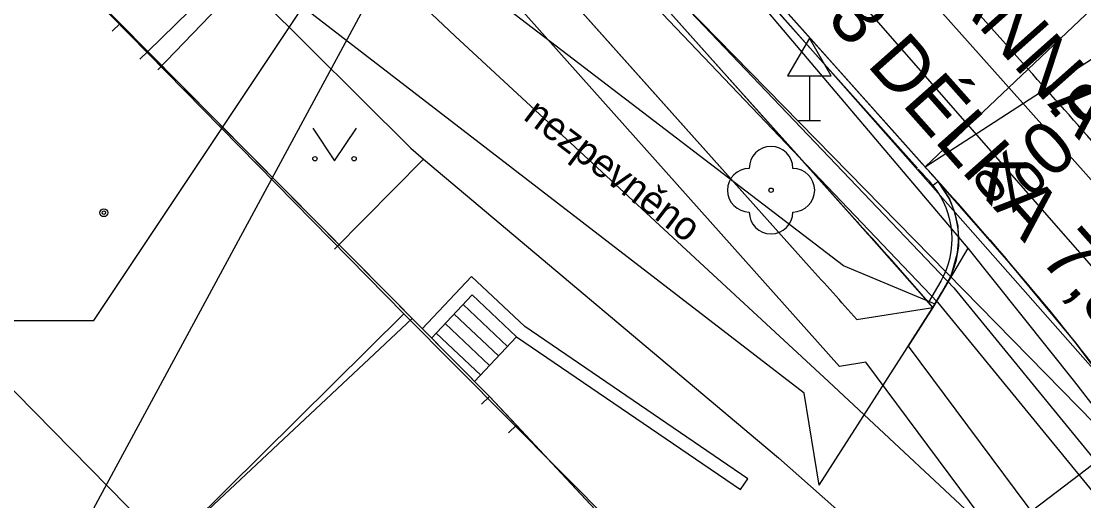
# Model space of a CAD drawing. Extents: x -643342 to -638635, y -1201752 to -1189948.
# Drawn here: x -639555.87 to -639531.53, y -1192591.39 to -1192580.4 of the extents above; entities that cross this region are included whole.
import ezdxf

# ---------------------------------------------------------------- set-up
doc = ezdxf.new("R2010")
doc.units = 0
for name, color, linetype in [('42', 7, 'Continuous'), ('IS_PLYN_STL', 7, 'Continuous'), ('IS_TELEF_MISTNI_ZAMERENO', 7, 'Continuous'), ('IS_VODOVOD_PRIPOJKA DOMOVNÍ', 7, 'Continuous'), ('IS_VODOVOD_VAS', 7, 'Continuous'), ('IS_VODOVOD_ZRUSENY', 7, 'Continuous'), ('K-HRANICE_KN', 7, 'Continuous'), ('N-CHODNIK', 7, 'Continuous'), ('N-KAN_DEST_TRASA-NÁVRH', 7, 'Continuous'), ('N-OBVOD STAVBY 06', 7, 'Continuous'), ('N-OSA', 7, 'Continuous'), ('N-SILNICE', 7, 'Continuous'), ('N-SJEZDY', 7, 'Continuous'), ('N-SO101_KLOPENI', 7, 'Continuous'), ('N-SRAFY_PLOCHY', 7, 'Continuous'), ('N-SVAHOVÁNÍ', 7, 'Continuous'), ('tomaštík - Džuganovi - Vrstva 36', 7, 'Continuous'), ('Z-budovy', 7, 'Continuous'), ('Z-hrany_a_čáry', 7, 'Continuous'), ('Z-popisy', 7, 'Continuous'), ('Z-stromy', 7, 'Continuous'), ('Z-vchody_vjezdy', 7, 'Continuous'), ('Z-značky', 7, 'Continuous')]:
    doc.layers.add(name, color=color, linetype=linetype)

msp = doc.modelspace()

# ---------------------------------------------------------------- linework, layer by layer
at = {"layer": '42'}
for p, q in [((-639555.166, -1192593.331), (-639544.715, -1192573.992)), ((-639540.313, -1192573.957), (-639523.758, -1192592.58)), ((-639554.206, -1192587.256), (-639546.647, -1192575.917)), ((-639601.668, -1192587.256), (-639554.206, -1192587.256))]:
    msp.add_line(p, q, dxfattribs=at)
at = {"layer": 'IS_PLYN_STL'}
msp.add_lwpolyline([(-639559.68, -1192568.38), (-639559.46, -1192568.55), (-639554.43, -1192572.9), (-639553.3, -1192573.86), (-639548.93, -1192577.94), (-639546.47, -1192580.23), (-639545.93, -1192580.74), (-639537.37, -1192588.65), (-639533.32, -1192592.44), (-639527.87, -1192598.3), (-639522.14, -1192604.57), (-639520.58, -1192607.01), (-639519.8, -1192608.6)], dxfattribs=at)
at = {"layer": 'IS_TELEF_MISTNI_ZAMERENO'}
for p, q in [((-639550.79, -1192579.48), (-639552.74, -1192581.51)), ((-639550.79, -1192579.48), (-639546.94, -1192583.31)), ((-639546.94, -1192583.31), (-639546.65, -1192583.56)), ((-639548.69, -1192585.62), (-639546.65, -1192583.56)), ((-639546.65, -1192583.56), (-639538.52, -1192590.4)), ((-639538.52, -1192590.4), (-639534.16, -1192594.26)), ((-639534.16, -1192594.26), (-639538.52, -1192590.4))]:
    msp.add_line(p, q, dxfattribs=at)
at = {"layer": 'IS_VODOVOD_PRIPOJKA DOMOVNÍ'}
msp.add_lwpolyline([(-639531.24, -1192590.494), (-639531.458, -1192590.659), (-639551.224, -1192605.705)], dxfattribs=at)
at = {"layer": 'IS_VODOVOD_VAS'}
for points in [[(-639574.178, -1192545), (-639565.32, -1192554.2), (-639544.196, -1192576.345), (-639543.991, -1192576.56), (-639543.73, -1192576.83), (-639534.504, -1192586.506), (-639531.24, -1192590.494), (-639527.133, -1192595.51), (-639522.796, -1192601.597), (-639522.77, -1192601.637), (-639518.91, -1192607.22), (-639515.881, -1192615.376)], [(-639574.504, -1192545.287), (-639565.62, -1192554.6), (-639534.876, -1192586.834), (-639527.527, -1192595.81), (-639523.229, -1192601.871), (-639519.29, -1192607.54), (-639519.07, -1192608.24), (-639516.818, -1192614.307), (-639515.63, -1192618.18), (-639513.05, -1192632.38), (-639511.6, -1192653.11)]]:
    msp.add_lwpolyline(points, dxfattribs=at)
at = {"layer": 'IS_VODOVOD_ZRUSENY'}
msp.add_lwpolyline([(-639573.944, -1192546.368), (-639550.08, -1192573.56), (-639545.32, -1192575.03), (-639544.04, -1192576.59), (-639530.53, -1192590.38), (-639522.03, -1192601.36), (-639515.23, -1192614.43)], dxfattribs=at)
at = {"layer": 'K-HRANICE_KN'}
for p, q in [((-639524.691, -1192595.875), (-639564.643, -1192550.549)), ((-639524.691, -1192595.875), (-639564.643, -1192550.549)), ((-639547.1, -1192587.1), (-639562.65, -1192571.27)), ((-639545.14, -1192589), (-639561.72, -1192572.25)), ((-639567.14, -1192577.61), (-639552.51, -1192592.45)), ((-639567.14, -1192577.61), (-639552.51, -1192592.45)), ((-639547.1, -1192587.1), (-639552.423, -1192592.372)), ((-639541.039, -1192593.2), (-639547.1, -1192587.1)), ((-639546.916, -1192587.206), (-639552.423, -1192592.372)), ((-639540.559, -1192593.892), (-639545.14, -1192589))]:
    msp.add_line(p, q, dxfattribs=at)
at = {"layer": 'N-CHODNIK'}
for p, q in [((-639536.716, -1192584.996), (-639544.403, -1192576.389)), ((-639536.716, -1192584.996), (-639536.686, -1192585.03)), ((-639534.799, -1192586.357), (-639535.085, -1192586.838)), ((-639534.67, -1192586.433), (-639534.982, -1192586.958))]:
    msp.add_line(p, q, dxfattribs=at)
msp.add_arc((-639605.834, -1192647.866), 93.434, 40.68372, 42.26147, dxfattribs=at)
at = {"layer": 'N-KAN_DEST_TRASA-NÁVRH'}
msp.add_lwpolyline([(-639583.962, -1192528.01), (-639550.452, -1192564.184), (-639529.583, -1192588.026), (-639514.491, -1192612.048), (-639507.737, -1192644.326), (-639498.832, -1192694.254), (-639511.439, -1192713.331), (-639516.613, -1192716.507), (-639553.938, -1192703.739), (-639570.485, -1192701.616), (-639578.687, -1192703.18)], dxfattribs=at)
at = {"layer": 'N-OBVOD STAVBY 06'}
msp.add_lwpolyline([(-639532.853, -1192592.991), (-639532.948, -1192593.015), (-639536.515, -1192588.213), (-639537.119, -1192588.308), (-639546.267, -1192578.054), (-639553.229, -1192570.356), (-639556.749, -1192566.564), (-639568.569, -1192553.875), (-639568.389, -1192552.802), (-639591.813, -1192527.078)], dxfattribs=at)
at = {"layer": 'N-OSA'}
msp.add_lwpolyline([(-639532.8, -1192581.5), (-639540.487, -1192572.892)], dxfattribs=at)
msp.add_arc((-639605.834, -1192647.866), 98.684, 39.35849, 42.26147, dxfattribs=at)
at = {"layer": 'N-SILNICE'}
for p, q in [((-639535.336, -1192583.764), (-639543.023, -1192575.157)), ((-639535.224, -1192583.664), (-639542.911, -1192575.057)), ((-639534.858, -1192584.07), (-639534.974, -1192584.164))]:
    msp.add_line(p, q, dxfattribs=at)
for centre, radius, start, end in [((-639605.834, -1192647.866), 95.434, 39.35849, 42.26147), ((-639605.834, -1192647.866), 95.434, 41.95008, 42.26147), ((-639605.834, -1192647.866), 95.284, 41.95008, 42.26147), ((-639536.489, -1192585.389), 1.948, 330.1366, 38.9464), ((-639536.489, -1192585.389), 1.948, 330.1366, 38.9464), ((-639536.489, -1192585.389), 2.098, 330.1366, 38.9464), ((-639568.444, -1192616.683), 46.75, 36.2973, 38.9025)]:
    msp.add_arc(centre, radius, start, end, dxfattribs=at)
at = {"layer": 'N-SJEZDY'}
for q in [(-639534.982, -1192586.958), (-639532.542, -1192591.885)]:
    msp.add_line((-639535.546, -1192587.841), q, dxfattribs=at)
at = {"layer": 'N-SO101_KLOPENI'}
msp.add_lwpolyline([(-639530.444, -1192579.261), (-639535.156, -1192583.738), (-639529.593, -1192580.131), (-639530.444, -1192579.261)], close=True, dxfattribs=at)
at = {"layer": 'N-SRAFY_PLOCHY'}
for p, q in [((-639536.701, -1192585.014), (-639544.404, -1192576.387)), ((-639545.521, -1192577.388), (-639537.815, -1192586.018)), ((-639539.873, -1192578.459), (-639537.91, -1192580.656)), ((-639537.91, -1192580.656), (-639536.454, -1192582.287)), ((-639536.454, -1192582.287), (-639534.858, -1192584.07)), ((-639534.858, -1192584.07), (-639533.68, -1192585.405)), ((-639533.228, -1192585.931), (-639534.858, -1192584.07)), ((-639534.858, -1192584.07), (-639534.604, -1192584.468)), ((-639534.604, -1192584.468), (-639534.484, -1192584.773)), ((-639534.484, -1192584.773), (-639534.412, -1192585.092)), ((-639534.412, -1192585.092), (-639534.397, -1192585.549)), ((-639533.68, -1192585.405), (-639532.303, -1192587.032)), ((-639534.397, -1192585.549), (-639534.455, -1192585.9)), ((-639534.455, -1192585.9), (-639534.576, -1192586.249)), ((-639531.744, -1192587.723), (-639533.228, -1192585.931)), ((-639534.576, -1192586.249), (-639534.766, -1192586.594)), ((-639534.766, -1192586.594), (-639534.982, -1192586.958)), ((-639536.729, -1192587.234), (-639534.982, -1192586.958)), ((-639534.982, -1192586.958), (-639535.546, -1192587.841)), ((-639532.303, -1192587.032), (-639531.432, -1192588.123)), ((-639535.546, -1192587.841), (-639532.542, -1192591.885)), ((-639530.531, -1192589.336), (-639531.744, -1192587.723))]:
    msp.add_line(p, q, dxfattribs=at)
msp.add_lwpolyline([(-639541.964, -1192579.119), (-639539.83, -1192581.51), (-639538.109, -1192583.436), (-639536.686, -1192585.03), (-639534.982, -1192586.958), (-639534.782, -1192586.622), (-639534.567, -1192586.229), (-639534.416, -1192585.707), (-639534.391, -1192585.368), (-639534.414, -1192585.082), (-639534.487, -1192584.761), (-639534.605, -1192584.466), (-639534.858, -1192584.07), (-639535.863, -1192582.949), (-639537.304, -1192581.336), (-639538.832, -1192579.625)], dxfattribs=at)
for radius, start, end in [(93.434, 40.68372, 42.27523), (91.934, 41.26308, 42.27938)]:
    msp.add_arc((-639605.834, -1192647.866), radius, start, end, dxfattribs=at)
at = {"layer": 'N-SVAHOVÁNÍ'}
msp.add_line((-639536.729, -1192587.234), (-639534.982, -1192586.958), dxfattribs=at)
msp.add_lwpolyline([(-639537.815, -1192586.018), (-639545.521, -1192577.388)], dxfattribs=at)
msp.add_arc((-639605.834, -1192647.866), 91.934, 41.26308, 42.27938, dxfattribs=at)
at = {"layer": 'Z-budovy'}
for p, q in [((-639553.604, -1192580.449), (-639557.02, -1192576.998)), ((-639552.971, -1192581.089), (-639553.604, -1192580.449)), ((-639545.14, -1192589), (-639552.971, -1192581.089)), ((-639544.525, -1192589.657), (-639545.14, -1192589)), ((-639540.559, -1192593.892), (-639544.525, -1192589.657))]:
    msp.add_line(p, q, dxfattribs=at)
at = {"layer": 'Z-hrany_a_čáry'}
for p, q in [((-639534.17, -1192585.6), (-639548.17, -1192569.06)), ((-639537.03, -1192586), (-639548.94, -1192576.89)), ((-639550.82, -1192578.99), (-639552.971, -1192581.089)), ((-639537.93, -1192588.92), (-639550.82, -1192578.99)), ((-639534.93, -1192586.88), (-639534.17, -1192585.6)), ((-639531.73, -1192588.66), (-639534.17, -1192585.6)), ((-639534.93, -1192586.88), (-639537.03, -1192586)), ((-639545.553, -1192586.246), (-639546.68, -1192587.444)), ((-639544.332, -1192587.395), (-639545.553, -1192586.246)), ((-639545.54, -1192586.67), (-639546.469, -1192587.657)), ((-639545.746, -1192586.888), (-639544.726, -1192587.848)), ((-639544.52, -1192587.63), (-639545.54, -1192586.67)), ((-639537.59, -1192591.03), (-639534.93, -1192586.88)), ((-639545.951, -1192587.107), (-639544.931, -1192588.067)), ((-639546.157, -1192587.325), (-639545.137, -1192588.285)), ((-639546.362, -1192587.544), (-639545.342, -1192588.504)), ((-639545.483, -1192588.653), (-639544.52, -1192587.63)), ((-639544.52, -1192587.63), (-639539.39, -1192591.13)), ((-639539.221, -1192590.882), (-639544.332, -1192587.395)), ((-639529.11, -1192592.06), (-639531.73, -1192588.66)), ((-639537.59, -1192591.03), (-639537.93, -1192588.92)), ((-639539.39, -1192591.13), (-639539.221, -1192590.882))]:
    msp.add_line(p, q, dxfattribs=at)
at = {"layer": 'Z-stromy'}
msp.add_circle((-639538.69, -1192584.27), 0.05, dxfattribs=at)
for centre, start, end in [((-639538.69, -1192583.77), 0, 180), ((-639539.19, -1192584.27), 90, 270), ((-639538.19, -1192584.27), 270, 90), ((-639538.69, -1192584.77), 180, 0)]:
    msp.add_arc(centre, 0.5, start, end, dxfattribs=at)
at = {"layer": 'Z-vchody_vjezdy'}
for p, q in [((-639553.782, -1192580.625), (-639553.604, -1192580.449)), ((-639552.971, -1192581.089), (-639553.604, -1192580.449)), ((-639553.149, -1192581.265), (-639552.971, -1192581.089)), ((-639545.323, -1192589.171), (-639545.14, -1192589)), ((-639544.525, -1192589.657), (-639545.14, -1192589)), ((-639544.708, -1192589.828), (-639544.525, -1192589.657))]:
    msp.add_line(p, q, dxfattribs=at)
at = {"layer": 'Z-značky'}
for p, q in [((-639537.81, -1192580.786), (-639538.31, -1192581.652)), ((-639537.31, -1192581.652), (-639537.81, -1192580.786)), ((-639538.31, -1192581.652), (-639537.31, -1192581.652)), ((-639537.81, -1192581.652), (-639537.81, -1192582.67)), ((-639538.06, -1192582.67), (-639537.56, -1192582.67)), ((-639549.191, -1192582.849), (-639548.691, -1192583.599)), ((-639548.691, -1192583.599), (-639548.191, -1192582.849))]:
    msp.add_line(p, q, dxfattribs=at)
for centre, radius in [((-639549.141, -1192583.549), 0.05), ((-639548.242, -1192583.549), 0.05), ((-639553.976, -1192584.786), 0.09), ((-639553.976, -1192584.786), 0.0398)]:
    msp.add_circle(centre, radius, dxfattribs=at)

# ---------------------------------------------------------------- texts
at = {"layer": 'N-SO101_KLOPENI'}
msp.add_text('5.0%', height=1.2, rotation=220.9782, dxfattribs=at).set_placement((-639531.392, -1192581.683))
at = {"layer": 'tomaštík - Džuganovi - Vrstva 36'}
for s, p in [('OCHRANNÁ TRUBKA ', (-639537.982, -1192575.987)), ('PE 63 DÉLKA 7,8 m', (-639539.85, -1192577.648))]:
    msp.add_text(s, height=1.25, rotation=311.6287, dxfattribs=at).set_placement(p)
at = {"layer": 'Z-popisy'}
msp.add_text('nezpevněno', height=0.65, rotation=322.8289, dxfattribs=at).set_placement((-639544.393, -1192582.631))

doc.saveas('drawing.dxf')
